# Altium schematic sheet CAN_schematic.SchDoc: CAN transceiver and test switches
size A4; Organization: UFSC; DocumentNumber: 5; SheetNumber: 5; SheetTotal: 8
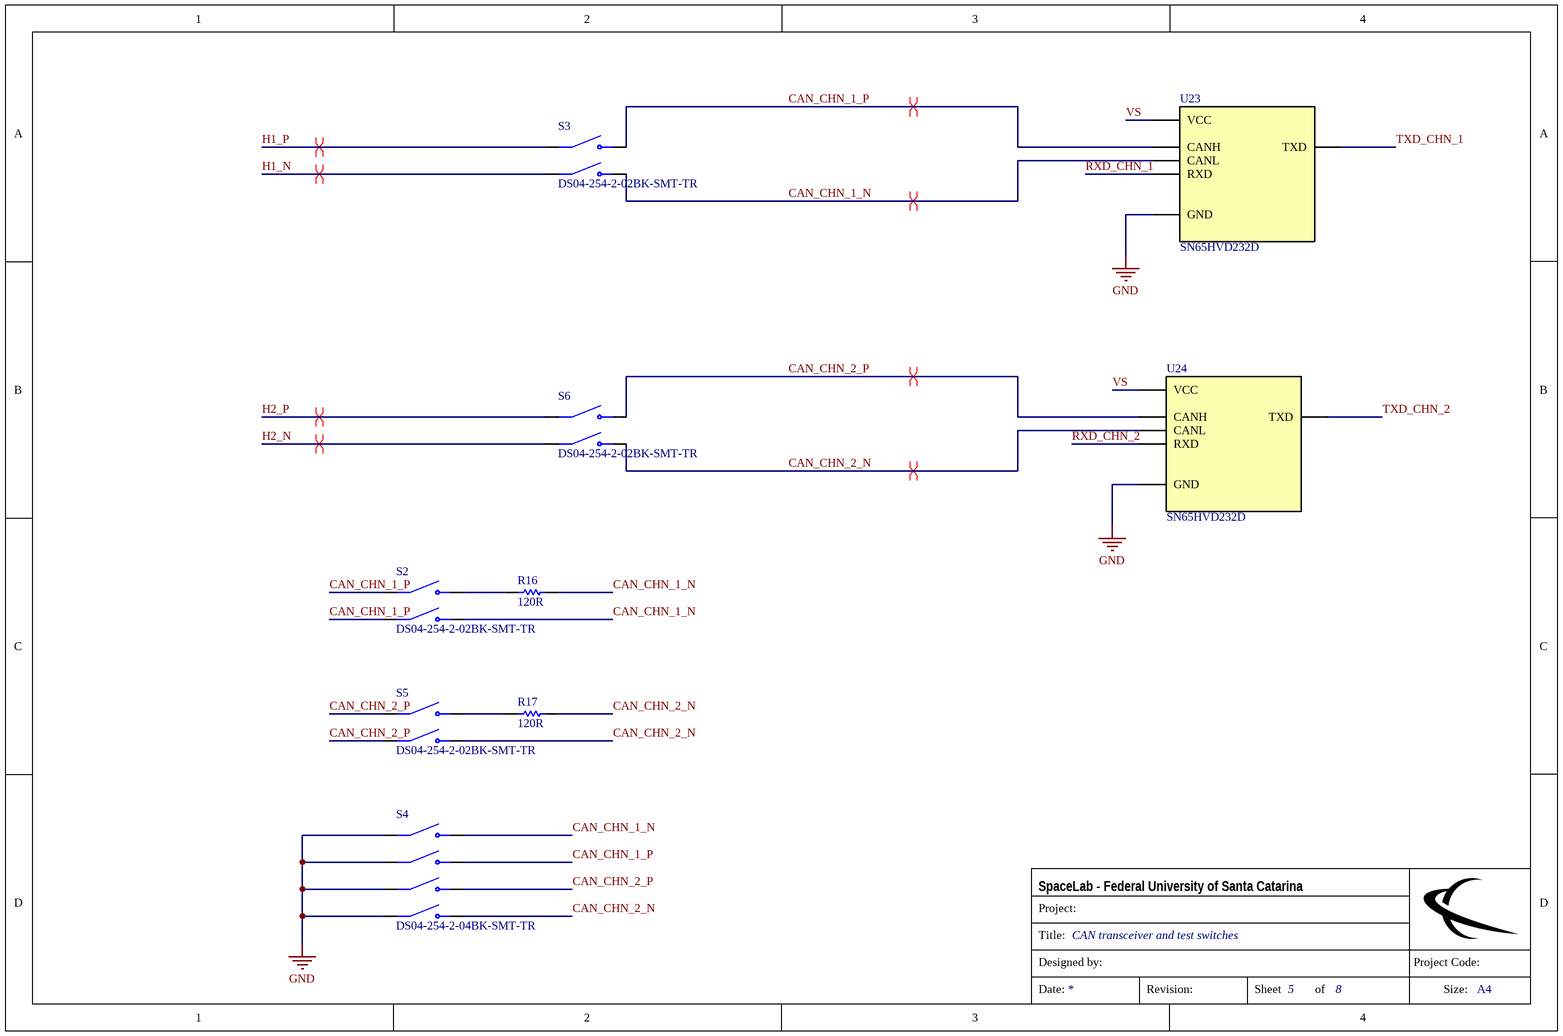
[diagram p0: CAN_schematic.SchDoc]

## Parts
R16  120R  [0805]
R17  120R  [0805]
S2  DS04-254-2-02BK-SMT-TR  [SW_DS04-254-2-02BK-SMT-TR]
S3  DS04-254-2-02BK-SMT-TR  [SW_DS04-254-2-02BK-SMT-TR]
S4  DS04-254-2-04BK-SMT-TR  [SW_DS04-254-2-04BK-SMT-TR]
S5  DS04-254-2-02BK-SMT-TR  [SW_DS04-254-2-02BK-SMT-TR]
S6  DS04-254-2-02BK-SMT-TR  [SW_DS04-254-2-02BK-SMT-TR]
U23  SN65HVD232D  [SOIC127P599X175-8N]
U24  SN65HVD232D  [SOIC127P599X175-8N]

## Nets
GND: S4.1A(COM1) S4.2A(COM2) S4.3A(COM3) S4.4A(COM4) U23.2(GND) U24.2(GND)
CAN_CHN_1_N: R16.1 S2.2B(NO2) S3.2B(NO2) S4.1B(NO1) U23.6(CANL)
CAN_CHN_1_P: S2.1A(COM1) S2.2A(COM2) S3.1B(NO1) S4.2B(NO2) U23.7(CANH)
CAN_CHN_2_N: R17.1 S4.4B(NO4) S5.2B(NO2) S6.2B(NO2) U24.6(CANL)
CAN_CHN_2_P: S4.3B(NO3) S5.1A(COM1) S5.2A(COM2) S6.1B(NO1) U24.7(CANH)
H1_N: S3.2A(COM2)
H1_P: S3.1A(COM1)
H2_N: S6.2A(COM2)
H2_P: S6.1A(COM1)
RXD_CHN_1: U23.4(RXD)
RXD_CHN_2: U24.4(RXD)
TXD_CHN_1: U23.1(TXD)
TXD_CHN_2: U24.1(TXD)
VS: U23.3(VCC) U24.3(VCC)
NetR16_2: R16.2 S2.1B(NO1)
NetR17_2: R17.2 S5.1B(NO1)

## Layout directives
differential pair: CAN_CHN_1_N, CAN_CHN_1_P, CAN_CHN_2_N, CAN_CHN_2_P, H1_N, H1_P, H2_N, H2_P

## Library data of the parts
R16 R17 = R120R_1%_1/4W_0805: RES 120R OHM 1/8W 1% 0805; Manufacturer Part Number: CRGCQ0805F120R
S2 S3 S5 S6 = DS04-254-2-02BK-SMT-TR: 1 ~ 12 positions, Surface Mount, 2.54 mm Pitch, Slide Actuator, DIP Switch; MF: CUI Devices
S4 = DS04-254-2-04BK-SMT-TR: 1 ~ 12 positions, Surface Mount, 2.54 mm Pitch, Slide Actuator, DIP Switch; MF: CUI Devices
U23 U24 = SN65HVD232D: 3.3 V CAN Transceiver; MF: Texas Instruments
